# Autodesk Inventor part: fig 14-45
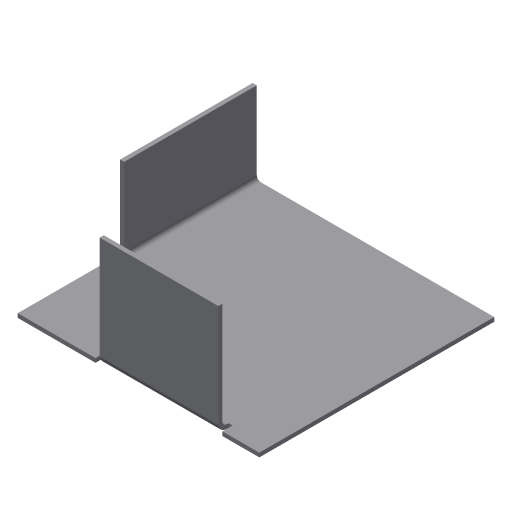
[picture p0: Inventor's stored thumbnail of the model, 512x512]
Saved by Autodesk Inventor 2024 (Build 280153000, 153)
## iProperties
Created: 2005-03
Part Number: fig 14-45
Document SubType Name: Sheet Metal
Designer: CADCIM
Manufacturer: Standard
Standards Organization: Custom
Density: 1 g/cm^3
Sheet Metal Rule: Default
Material: Generic
Appearance: Default
Author: CADCIM
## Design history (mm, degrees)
node "Face1"
  sketch "Sketch1"
    geometry: L1 (-29, -26)-(30, -26); L2 (30, -26)-(30, 31.375); L3 (30, 31.375)-(-29, 31.375); L4 (-29, 31.375)-(-29, -26)
    constraints: 8 end point, 2 parallel, 1 horizontal, 1 perpendicular
node "Flange1"
node "Flange2"
body "Solid1"
face "Plate1" dims "d19" = 1 (= Thickness)
sketch "Sketch2"
  geometry: L1 (25, 0)-(57.375, 0); L2 (57.375, 0)-(57.375, 20); L3 (57.375, 20)-(25, 20); L4 (25, 20)-(25, 0)
  constraints: 8 end point
face "Plate2" dims "d1" = 0, "d2" = 25, "d3" = 1 (= BendReliefWidth), "d5" = 2 (= MinimumRemnant), "d7" = 20, "d8" = 90 deg, "d9" = 1 (= BendRadius), "d19" = 1 (= Thickness)
bend "Bend1" dims "d3" = 1 (= BendReliefWidth), "d4" = 0.5 (= BendReliefDepth), "d5" = 2 (= MinimumRemnant), "d6" = 1 (= BendRadius), "d7" = 20, "d8" = 90 deg, "d9" = 1 (= BendRadius), "d19" = 1 (= Thickness), "SeamGap" = 0.01
sketch "Sketch3"
  geometry: L1 (10, 0)-(39, 0); L2 (39, 0)-(39, 26); L3 (39, 26)-(10, 26); L4 (10, 26)-(10, 0)
  constraints: 8 end point
face "Plate3" dims "d10" = 20, "d11" = 10, "d12" = 1 (= BendReliefWidth), "d14" = 2 (= MinimumRemnant), "d16" = 26, "d17" = 90 deg, "d18" = 1 (= BendRadius), "d19" = 1 (= Thickness)
bend "Bend2" dims "d12" = 1 (= BendReliefWidth), "d13" = 0.5 (= BendReliefDepth), "d14" = 2 (= MinimumRemnant), "d15" = 1 (= BendRadius), "d16" = 26, "d17" = 90 deg, "d18" = 1 (= BendRadius), "d19" = 1 (= Thickness), "SeamGap" = 0.01
other parameters: "Thickness" = 1, "BendRadius" = 1 (= Thickness), "BendReliefWidth" = 1 (= Thickness), "BendReliefDepth" = 0.5 (= 0.5 x Thickness), "CornerReliefSize" = 4 (= 4 x Thickness), "MinimumRemnant" = 2 (= 2 x Thickness), "TransitionRadius" = 1 (= BendRadius), "d0" = 1 (= BendRadius), "JacobiRadiusSize" = 1 (= Thickness), "GapSize" = 1 (= Thickness)
